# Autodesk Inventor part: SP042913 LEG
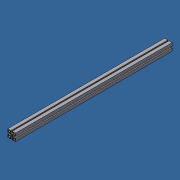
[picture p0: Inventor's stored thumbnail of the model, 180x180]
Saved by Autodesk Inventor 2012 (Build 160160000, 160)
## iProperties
Created: 2013-04
Part Number: SP042913 LEG
Material: Aluminum-6061
Description: PROFILE 45X45 F
Document SubType Name: Modeling
Designer: Admin
Stock Number: 20.1033 PROFILE 45X45 F
Density: 2.71 g/cm^3
FINISH: CLEAR ANODIZED
Author: Admin
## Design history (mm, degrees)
sketch "Sketch1"
  geometry: L1 (-4.1, -22.5)-(-4.1, -18) reference; L2 (-4.6, -18)-(-6.8, -18) reference; L3 (-6.8, -18)-(-6.8, -9.5) reference; L4 (-6.8, -9.5)-(-4.5, -7.2) reference; L5 (-4.5, -7.2)-(4.5, -7.2) reference; L6 (4.5, -7.2)-(6.8, -9.5) reference; L7 (6.8, -9.5)-(6.8, -18) reference; L8 (4.1, -18)-(4.1, -22.5) reference; L9 (22.5, -4.1)-(18, -4.1) reference; L10 (18, -4.6)-(18, -6.8) reference; L11 (18, -6.8)-(9.5, -6.8) reference; L12 (9.5, -6.8)-(7.2, -4.5) reference; L13 (7.2, -4.5)-(7.2, 4.5) reference; L14 (7.2, 4.5)-(9.5, 6.8) reference; L15 (9.5, 6.8)-(18, 6.8) reference; L16 (18, 4.1)-(22.5, 4.1) reference; L17 (22.5, 22.5)-(22.5, 4.4) reference; L18 (4.1, 22.5)-(4.1, 18) reference; L19 (4.6, 18)-(6.8, 18) reference; L20 (6.8, 18)-(6.8, 9.5) reference; L21 (6.8, 9.5)-(4.5, 7.2) reference; L22 (4.5, 7.2)-(-4.5, 7.2) reference; L23 (-4.5, 7.2)-(-6.8, 9.5) reference; L24 (-6.8, 9.5)-(-6.8, 18) reference; L25 (-4.1, 18)-(-4.1, 22.5) reference; L26 (-22.5, 22.5)-(-4.4, 22.5) reference; L27 (-22.5, 4.1)-(-18, 4.1) reference; L28 (-18, 6.8)-(-9.5, 6.8) reference; L29 (-9.5, 6.8)-(-7.2, 4.5) reference; L30 (-7.2, 4.5)-(-7.2, -4.5) reference; L31 (-7.2, -4.5)-(-9.5, -6.8) reference; L32 (-9.5, -6.8)-(-18, -6.8) reference; L33 (-18, -6.8)-(-18, -4.6) reference; L34 (-18, -4.1)-(-22.5, -4.1) reference; L35 (-22.5, -22.5)-(-22.5, -4.4) reference; L36 (-4.4, -22.5)-(-22.5, -22.5) reference; L37 (-4.596, -3.182)-(-3.263, -1.849) reference; L38 (-3.263, 1.849)-(-4.596, 3.182) reference; L39 (-4.596, 3.182)-(-3.182, 4.596) reference; L40 (-3.182, 4.596)-(-1.849, 3.263) reference; L41 (1.849, 3.263)-(3.182, 4.596) reference; L42 (3.182, 4.596)-(4.596, 3.182) reference; L43 (4.596, 3.182)-(3.263, 1.849) reference; L44 (3.263, -1.849)-(4.596, -3.182) reference; L45 (4.596, -3.182)-(3.182, -4.596) reference; L46 (3.182, -4.596)-(1.849, -3.263) reference; L47 (-1.849, -3.263)-(-3.182, -4.596) reference; L48 (-3.182, -4.596)-(-4.596, -3.182) reference; L49 (13.8, -8.8)-(20.5, -8.8) reference; L50 (20.5, -8.8)-(20.5, -15.5) reference; L51 (15.5, -20.5)-(8.8, -20.5) reference; L52 (8.8, -20.5)-(8.8, -13.8) reference; L53 (8.8, 13.8)-(8.8, 20.5) reference; L54 (8.8, 20.5)-(15.5, 20.5) reference; L55 (20.5, 15.5)-(20.5, 8.8) reference; L56 (20.5, 8.8)-(13.8, 8.8) reference; L57 (-13.8, 8.8)-(-20.5, 8.8) reference; L58 (-20.5, 8.8)-(-20.5, 15.5) reference; L59 (-15.5, 20.5)-(-8.8, 20.5) reference; L60 (-8.8, 20.5)-(-8.8, 13.8) reference; L61 (-8.8, -13.8)-(-8.8, -20.5) reference; L62 (-8.8, -20.5)-(-15.5, -20.5) reference; L63 (-20.5, -15.5)-(-20.5, -8.8) reference; L64 (-20.5, -8.8)-(-13.8, -8.8) reference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; A1 r 3.75 centre (0, 0) between (3.362, -1.66) and (3.362, 1.66) reference; A2 r 5 centre (13.8, -13.8) between (13.8, -8.8) and (8.8, -13.8) reference; A3 r 5 centre (15.5, -15.5) between (15.5, -20.5) and (20.5, -15.5) reference; A4 r 5 centre (13.8, 13.8) between (8.8, 13.8) and (13.8, 8.8) reference; A5 r 5 centre (15.5, 15.5) between (20.5, 15.5) and (15.5, 20.5) reference; A6 r 5 centre (-13.8, 13.8) between (-13.8, 8.8) and (-8.8, 13.8) reference; A7 r 5 centre (-15.5, 15.5) between (-15.5, 20.5) and (-20.5, 15.5) reference; A8 r 5 centre (-13.8, -13.8) between (-8.8, -13.8) and (-13.8, -8.8) reference; A9 r 5 centre (-15.5, -15.5) between (-20.5, -15.5) and (-15.5, -20.5) reference; A10 r 3.75 centre (0, 0) between (3.362, 1.66) and (3.263, 1.849) reference; A11 r 3.75 centre (0, 0) between (1.849, 3.263) and (-1.66, 3.362) reference; A12 r 3.75 centre (0, 0) between (-1.66, 3.362) and (-1.849, 3.263) reference; A13 r 3.75 centre (0, 0) between (-3.263, 1.849) and (-3.263, -1.849) reference; A14 r 3.75 centre (0, 0) between (-1.849, -3.263) and (-1.66, -3.362) reference; A15 r 3.75 centre (0, 0) between (-1.66, -3.362) and (1.849, -3.263) reference; A16 r 3.75 centre (0, 0) between (3.263, -1.849) and (3.362, -1.66) reference
  constraints: 160 end point, 32 point on circle, 30 horizontal, 30 vertical, 16 centre point, 144 other
extrude "Extrusion1" new body sketch "Sketch1" distance "d0" = 1009.65 (= -LEVELER_HEIGHT + Height - TABLE_TOP_THICKNESS); taper "d1" = 0 deg
body "Solid1"
other parameters: "Height" = 1066.8 [user parameter; used in 1 equation term], "Width" = 1828.8 [user parameter], "DEPTH" = 914.4 [user parameter], "LOWER_INSET" = 203.2 [user parameter], "TABLE_TOP_THICKNESS" = 12.7 [user parameter; used in 1 equation term], "LEVELER_HEIGHT" = 44.45 [user parameter; used in 1 equation term], "TOP_OVERHANG" = 25.4 [user parameter]
